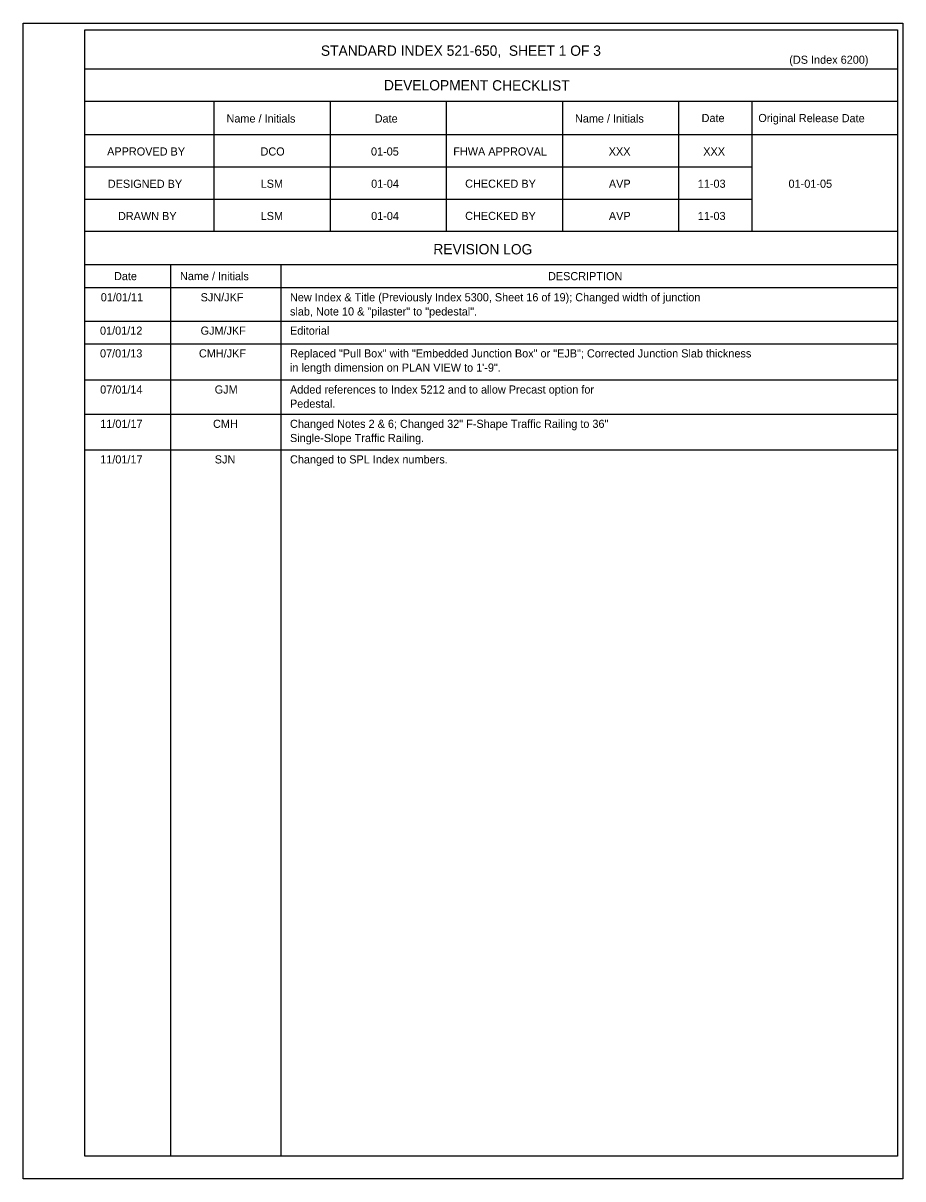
# Model space of a CAD drawing. Extents: x 0 to 54.1, y -0.5 to 22.5.
# Drawn here: x 37.73 to 54.09, y -0.49 to 21.01 of the extents above; entities that cross this region are included whole.
import ezdxf

# ---------------------------------------------------------------- set-up
doc = ezdxf.new("R2010")
doc.units = 0
for name, color, linetype in [('Border', 7, 'Continuous'), ('PlotBorder_dp', 7, 'Continuous'), ('TextStructures', 7, 'Continuous')]:
    doc.layers.add(name, color=color, linetype=linetype)

msp = doc.modelspace()

# ---------------------------------------------------------------- linework, layer by layer
at = {"layer": 'Border'}
for p, q in [((53.991, 20.153), (38.881, 20.153)), ((53.991, 19.553), (38.881, 19.553)), ((41.281, 19.553), (41.281, 17.132)), ((43.441, 19.553), (43.441, 17.132)), ((45.601, 19.553), (45.601, 17.132)), ((47.761, 19.553), (47.761, 17.132)), ((49.921, 19.553), (49.921, 17.132)), ((51.282, 19.553), (51.282, 17.132)), ((53.991, 18.932), (38.881, 18.932)), ((51.282, 18.332), (38.881, 18.332)), ((51.282, 17.732), (38.881, 17.732)), ((53.991, 17.132), (38.881, 17.132)), ((53.991, 16.511), (38.881, 16.511)), ((40.471, 16.511), (40.471, -0.069)), ((42.528, 16.511), (42.528, -0.069)), ((53.991, 16.088), (38.881, 16.088))]:
    msp.add_line(p, q, dxfattribs=at)
msp.add_lwpolyline([(38.881, 20.888), (53.991, 20.888), (53.991, -0.069), (38.881, -0.069)], close=True, dxfattribs=at)
at = {"layer": 'PlotBorder_dp'}
msp.add_line((37.733, -0.49), (37.733, -0.49), dxfattribs=at)
msp.add_lwpolyline([(37.733, 21.01), (54.093, 21.01), (54.093, -0.49), (37.733, -0.49)], close=True, dxfattribs=at)
at = {"layer": 'TextStructures'}
for p, q in [((38.881, 15.467), (53.991, 15.467)), ((38.881, 15.045), (53.991, 15.045)), ((38.881, 14.373), (53.991, 14.373)), ((38.881, 13.735), (53.991, 13.735)), ((38.881, 13.073), (53.991, 13.073))]:
    msp.add_line(p, q, dxfattribs=at)

# ---------------------------------------------------------------- texts
for s, height, p in [('STANDARD INDEX 521-650,  SHEET 1 OF 3', 0.192, (43.27, 20.402)), ('(DS Index 6200)', 0.1512, (51.981, 20.254)), ('DCO', 0.1512, (42.148, 18.547)), ('01-05', 0.1512, (44.202, 18.547)), ('XXX', 0.1512, (48.623, 18.547)), ('XXX', 0.1512, (50.381, 18.547)), ('LSM', 0.1512, (42.151, 17.947)), ('01-04', 0.1512, (44.205, 17.947)), ('AVP', 0.1512, (48.626, 17.947)), ('11-03', 0.1512, (50.279, 17.947)), ('01-01-05', 0.1512, (51.967, 17.947)), ('LSM', 0.1512, (42.151, 17.347)), ('01-04', 0.1512, (44.205, 17.347)), ('AVP', 0.1512, (48.626, 17.347)), ('11-03', 0.1512, (50.279, 17.347)), ('DESCRIPTION', 0.1512, (47.494, 16.228)), ('01/01/11', 0.1512, (39.177, 15.835)), ('SJN/JKF', 0.1512, (41.034, 15.835)), ('New Index & Title (Previously Index 5300, Sheet 16 of 19); Changed width of junction', 0.1512, (42.696, 15.835)), ('slab, Note 10 & "pilaster" to "pedestal".', 0.1512, (42.696, 15.571)), ('01/01/12', 0.1512, (39.163, 15.214)), ('GJM/JKF', 0.1512, (41.033, 15.214)), ('Editorial', 0.1512, (42.696, 15.214)), ('07/01/13', 0.1512, (39.163, 14.791)), ('CMH/JKF', 0.1512, (41.002, 14.791)), ('Replaced "Pull Box" with "Embedded Junction Box" or "EJB"; Corrected Junction Slab thickness', 0.1512, (42.696, 14.791)), ('in length dimension on PLAN VIEW to 1\'-9".', 0.1512, (42.696, 14.527)), ('07/01/14', 0.1512, (39.166, 14.119)), ('GJM', 0.1512, (41.296, 14.119)), ('Added references to Index 5212 and to allow Precast option for ', 0.1512, (42.696, 14.119)), ('Pedestal. ', 0.1512, (42.696, 13.856)), ('11/01/17', 0.1512, (39.167, 13.481)), ('CMH', 0.1512, (41.265, 13.481)), ('Changed Notes 2 & 6; Changed 32" F-Shape Traffic Railing to 36" ', 0.1512, (42.696, 13.481)), ('Single-Slope Traffic Railing.', 0.1512, (42.696, 13.217)), ('11/01/17', 0.1512, (39.167, 12.819)), ('SJN', 0.1512, (41.297, 12.819)), ('Changed to SPL Index numbers.', 0.1512, (42.696, 12.819))]:
    msp.add_text(s, height=height, dxfattribs=at).set_placement(p)
for s, height, p in [('DEVELOPMENT CHECKLIST', 0.192, (44.443, 19.761)), ('Name / Initials', 0.1512, (41.515, 19.162)), ('Date', 0.1512, (44.271, 19.161)), ('Name / Initials', 0.1512, (47.995, 19.162)), ('Date', 0.1512, (50.35, 19.17)), ('Original Release Date', 0.1512, (51.405, 19.17)), ('APPROVED BY', 0.1512, (39.295, 18.549)), ('FHWA APPROVAL', 0.1512, (45.732, 18.549)), ('DESIGNED BY', 0.1512, (39.308, 17.947)), ('CHECKED BY', 0.1512, (45.953, 17.949)), ('DRAWN BY', 0.1512, (39.497, 17.347)), ('CHECKED BY', 0.1512, (45.953, 17.349)), ('REVISION LOG', 0.192, (45.362, 16.711)), ('Date', 0.1512, (39.423, 16.229)), ('Name / Initials', 0.1512, (40.65, 16.23))]:
    msp.add_text(s, height=height, rotation=359.8756, dxfattribs=at).set_placement(p)

doc.saveas('drawing.dxf')
